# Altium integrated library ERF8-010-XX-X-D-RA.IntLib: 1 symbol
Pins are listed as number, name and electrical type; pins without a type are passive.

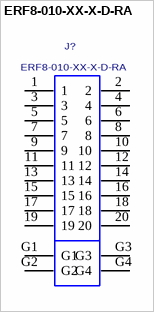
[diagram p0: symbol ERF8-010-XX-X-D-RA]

## ERF8-010-XX-X-D-RA
designator J?
0.8MM PITCH DUAL ROW RIGHT ANGLE SOCKET ASSEMBLY.; MANUFACTURER: SAMTEC
footprint ERF8-010-XX-X-D-RA
pins: 1, 2, 3, 4, 5, 6, 7, 8, 9, 10, 11, 12, 13, 14, 15, 16, 17, 18, 19, 20, G1, G2, G3, G4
